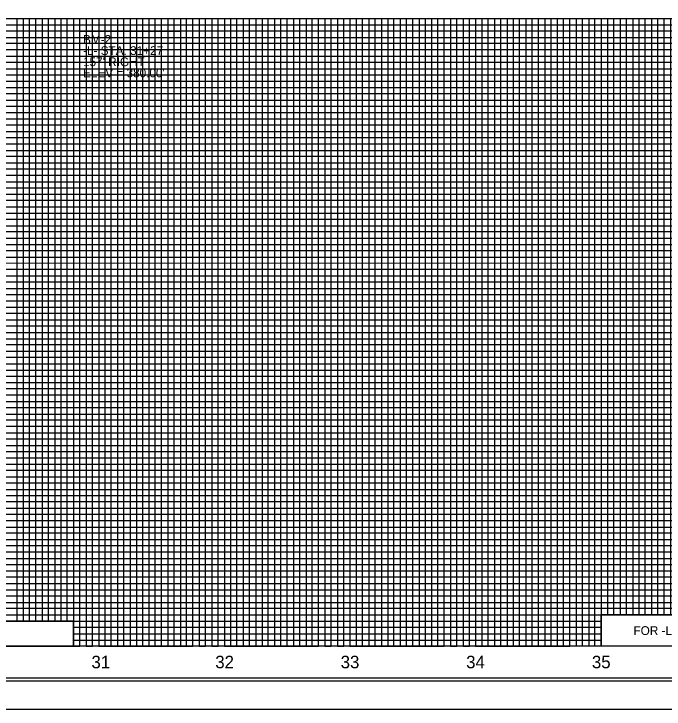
# Model space of a CAD drawing. Extents: x 1629887 to 1632095, y 1174261 to 1175361.
# Drawn here: x 1630837 to 1631354, y 1174261 to 1174814 of the extents above; entities that cross this region are included whole.
import ezdxf

# ---------------------------------------------------------------- set-up
doc = ezdxf.new("R2010")
doc.units = 0
for name, color, linetype in [('Exist Vertical Profile Horizontal Axis Label Major', 7, 'Continuous'), ('Prop DSN Text', 7, 'Continuous'), ('Prop Grid Mask', 7, 'Continuous'), ('Sheet Data Field CELL', 7, 'Continuous'), ('Sheet Layout Profile Border Port 2', 7, 'Continuous'), ('Sheet Plot Border Inside CELL', 7, 'Continuous'), ('Sheet Plot Border Outside CELL', 7, 'Continuous'), ('Sheet Profile CELL', 7, 'Continuous'), ('Sheet Profile Grid Major CELL', 7, 'Continuous'), ('Sheet Profile Grid Middle CELL', 7, 'Continuous'), ('Sheet Profile Grid Minor CELL', 7, 'Continuous')]:
    doc.layers.add(name, color=color, linetype=linetype)

msp = doc.modelspace()

# ---------------------------------------------------------------- linework, layer by layer
at = {"layer": 'Prop Grid Mask'}
msp.add_lwpolyline([(1630889.31, 1174800.79), (1630969.31, 1174800.79), (1630969.31, 1174760.79), (1630889.31, 1174760.79)], close=True, dxfattribs=at)
at = {"layer": 'Sheet Data Field CELL'}
for points in [[(1631504.31, 1174310.79), (1631304.31, 1174310.79), (1631304.31, 1174335.79), (1631504.31, 1174335.79)], [(1630724.31, 1174310.79), (1630884.31, 1174310.79), (1630884.31, 1174330.79), (1630724.31, 1174330.79)]]:
    msp.add_lwpolyline(points, close=True, dxfattribs=at)
at = {"layer": 'Sheet Layout Profile Border Port 2'}
msp.add_lwpolyline([(1630104.31, 1174810.79), (1631504.31, 1174810.79), (1631504.31, 1174335.79), (1631304.31, 1174335.79), (1631304.31, 1174310.79), (1630884.31, 1174310.79), (1630884.31, 1174330.79), (1630724.31, 1174330.79), (1630724.31, 1174310.79), (1630104.31, 1174310.79)], close=True, dxfattribs=at)
at = {"layer": 'Sheet Plot Border Inside CELL'}
msp.add_lwpolyline([(1629900.31, 1174283.24), (1631566.81, 1174283.24), (1631566.81, 1175338.34), (1629900.31, 1175338.34)], close=True, dxfattribs=at)
at = {"layer": 'Sheet Plot Border Outside CELL'}
msp.add_lwpolyline([(1629887.31, 1174260.79), (1631571.31, 1174260.79), (1631571.31, 1175360.79), (1629887.31, 1175360.79)], close=True, dxfattribs=at)
at = {"layer": 'Sheet Profile CELL'}
for p, q in [((1630054.31, 1174810.79), (1631554.31, 1174810.79)), ((1631554.31, 1174310.79), (1630054.31, 1174310.79)), ((1630054.31, 1174285.79), (1631554.31, 1174285.79))]:
    msp.add_line(p, q, dxfattribs=at)
msp.add_lwpolyline([(1631554.31, 1175335.79), (1630054.31, 1175335.79), (1630054.31, 1174285.79), (1631554.31, 1174285.79)], close=True, dxfattribs=at)
at = {"layer": 'Sheet Profile Grid Major CELL'}
for p, q in [((1630854.31, 1174810.79), (1630904.31, 1174810.79)), ((1630854.31, 1174330.79), (1630854.31, 1174810.79)), ((1630854.31, 1174810.79), (1630904.31, 1174810.79)), ((1630904.31, 1174810.79), (1630904.31, 1174310.79)), ((1630954.31, 1174810.79), (1631004.31, 1174810.79)), ((1630954.31, 1174310.79), (1630954.31, 1174810.79)), ((1630954.31, 1174810.79), (1631004.31, 1174810.79)), ((1631004.31, 1174810.79), (1631004.31, 1174310.79)), ((1631054.31, 1174810.79), (1631104.31, 1174810.79)), ((1631054.31, 1174310.79), (1631054.31, 1174810.79)), ((1631054.31, 1174810.79), (1631104.31, 1174810.79)), ((1631104.31, 1174810.79), (1631104.31, 1174310.79)), ((1631154.31, 1174810.79), (1631204.31, 1174810.79)), ((1631154.31, 1174310.79), (1631154.31, 1174810.79)), ((1631154.31, 1174810.79), (1631204.31, 1174810.79)), ((1631204.31, 1174810.79), (1631204.31, 1174310.79)), ((1631254.31, 1174810.79), (1631304.31, 1174810.79)), ((1631254.31, 1174310.79), (1631254.31, 1174810.79)), ((1631254.31, 1174810.79), (1631304.31, 1174810.79)), ((1631304.31, 1174810.79), (1631304.31, 1174310.79)), ((1630904.31, 1174310.79), (1630954.31, 1174310.79)), ((1631004.31, 1174310.79), (1631054.31, 1174310.79)), ((1631104.31, 1174310.79), (1631154.31, 1174310.79)), ((1631204.31, 1174310.79), (1631254.31, 1174310.79))]:
    msp.add_line(p, q, dxfattribs=at)
for points in [[(1631354.31, 1174335.79), (1631354.31, 1174810.79), (1631404.31, 1174810.79), (1631404.31, 1174335.79)], [(1631554.31, 1174785.79), (1630054.31, 1174785.79)], [(1631554.31, 1174735.79), (1630054.31, 1174735.79)], [(1631554.31, 1174685.79), (1630054.31, 1174685.79), (1630054.31, 1174635.79), (1631554.31, 1174635.79)], [(1631554.31, 1174585.79), (1630054.31, 1174585.79), (1630054.31, 1174535.79), (1631554.31, 1174535.79)], [(1631554.31, 1174485.79), (1630054.31, 1174485.79), (1630054.31, 1174435.79), (1631554.31, 1174435.79)], [(1631554.31, 1174385.79), (1630054.31, 1174385.79), (1630054.31, 1174385.79), (1630054.31, 1174335.79), (1631554.31, 1174335.79)], [(1631554.31, 1174310.79), (1630054.31, 1174310.79)]]:
    msp.add_lwpolyline(points, dxfattribs=at)
at = {"layer": 'Sheet Profile Grid Middle CELL'}
for points in [[(1630879.31, 1174330.79), (1630879.31, 1174810.79), (1630929.31, 1174810.79), (1630929.31, 1174310.79), (1630979.31, 1174310.79), (1630979.31, 1174810.79), (1631029.31, 1174810.79), (1631029.31, 1174310.79), (1631079.31, 1174310.79), (1631079.31, 1174810.79), (1631129.31, 1174810.79), (1631129.31, 1174310.79), (1631179.31, 1174310.79), (1631179.31, 1174810.79), (1631229.31, 1174810.79), (1631229.31, 1174310.79), (1631279.31, 1174310.79)], [(1631279.31, 1174310.79), (1631279.31, 1174810.79), (1631329.31, 1174810.79), (1631329.31, 1174335.79)], [(1630054.31, 1174760.79), (1631554.31, 1174760.79)], [(1631554.31, 1174710.79), (1630054.31, 1174710.79), (1630054.31, 1174660.79), (1631554.31, 1174660.79)], [(1631554.31, 1174610.79), (1630054.31, 1174610.79), (1630054.31, 1174560.79), (1631554.31, 1174560.79)], [(1631554.31, 1174510.79), (1630054.31, 1174510.79), (1630054.31, 1174460.79), (1631554.31, 1174460.79)], [(1631554.31, 1174410.79), (1630054.31, 1174410.79), (1630054.31, 1174360.79), (1631554.31, 1174360.79)], [(1631554.31, 1174310.79), (1630054.31, 1174310.79)]]:
    msp.add_lwpolyline(points, dxfattribs=at)
at = {"layer": 'Sheet Profile Grid Minor CELL'}
for p, q in [((1630849.31, 1174330.79), (1630849.31, 1174810.79)), ((1630849.31, 1174810.79), (1630859.31, 1174810.79)), ((1630859.31, 1174810.79), (1630859.31, 1174330.79)), ((1630864.31, 1174330.79), (1630864.31, 1174810.79)), ((1630864.31, 1174810.79), (1630869.31, 1174810.79)), ((1630869.31, 1174810.79), (1630869.31, 1174330.79)), ((1630874.31, 1174330.79), (1630874.31, 1174810.79)), ((1630874.31, 1174810.79), (1630884.31, 1174810.79)), ((1630884.31, 1174810.79), (1630884.31, 1174310.79)), ((1630889.31, 1174310.79), (1630889.31, 1174810.79)), ((1630889.31, 1174810.79), (1630894.31, 1174810.79)), ((1630894.31, 1174810.79), (1630894.31, 1174310.79)), ((1630899.31, 1174310.79), (1630899.31, 1174810.79)), ((1630899.31, 1174810.79), (1630909.31, 1174810.79)), ((1630909.31, 1174810.79), (1630909.31, 1174310.79)), ((1630914.31, 1174310.79), (1630914.31, 1174810.79)), ((1630914.31, 1174810.79), (1630919.31, 1174810.79)), ((1630919.31, 1174810.79), (1630919.31, 1174310.79)), ((1630924.31, 1174310.79), (1630924.31, 1174810.79)), ((1630924.31, 1174810.79), (1630934.31, 1174810.79)), ((1630934.31, 1174810.79), (1630934.31, 1174310.79)), ((1630104.31, 1174805.79), (1631504.31, 1174805.79)), ((1631504.31, 1174800.79), (1630104.31, 1174800.79)), ((1630104.31, 1174795.79), (1631504.31, 1174795.79)), ((1631504.31, 1174790.79), (1630104.31, 1174790.79)), ((1630104.31, 1174780.79), (1631504.31, 1174780.79)), ((1631504.31, 1174775.79), (1630104.31, 1174775.79)), ((1630104.31, 1174770.79), (1631504.31, 1174770.79)), ((1631504.31, 1174765.79), (1630104.31, 1174765.79)), ((1630104.31, 1174755.79), (1631504.31, 1174755.79)), ((1631504.31, 1174750.79), (1630104.31, 1174750.79)), ((1630104.31, 1174745.79), (1631504.31, 1174745.79)), ((1631504.31, 1174740.79), (1630104.31, 1174740.79)), ((1630104.31, 1174730.79), (1631504.31, 1174730.79)), ((1631504.31, 1174725.79), (1630104.31, 1174725.79)), ((1630104.31, 1174720.79), (1631504.31, 1174720.79)), ((1631504.31, 1174715.79), (1630104.31, 1174715.79)), ((1630104.31, 1174705.79), (1631504.31, 1174705.79)), ((1631504.31, 1174700.79), (1630104.31, 1174700.79)), ((1630104.31, 1174695.79), (1631504.31, 1174695.79)), ((1631504.31, 1174690.79), (1630104.31, 1174690.79)), ((1630104.31, 1174680.79), (1631504.31, 1174680.79)), ((1631504.31, 1174675.79), (1630104.31, 1174675.79)), ((1630104.31, 1174670.79), (1631504.31, 1174670.79)), ((1631504.31, 1174665.79), (1630104.31, 1174665.79)), ((1630104.31, 1174655.79), (1631504.31, 1174655.79)), ((1631504.31, 1174650.79), (1630104.31, 1174650.79)), ((1630104.31, 1174645.79), (1631504.31, 1174645.79)), ((1631504.31, 1174640.79), (1630104.31, 1174640.79)), ((1630104.31, 1174630.79), (1631504.31, 1174630.79)), ((1631504.31, 1174625.79), (1630104.31, 1174625.79)), ((1630104.31, 1174620.79), (1631504.31, 1174620.79)), ((1631504.31, 1174615.79), (1630104.31, 1174615.94)), ((1630104.31, 1174605.79), (1631504.31, 1174605.79)), ((1631504.31, 1174600.79), (1630104.31, 1174600.79)), ((1630104.31, 1174595.79), (1631504.31, 1174595.79)), ((1631504.31, 1174590.79), (1630104.31, 1174590.79)), ((1630104.31, 1174580.79), (1631504.31, 1174580.79)), ((1631504.31, 1174575.79), (1630104.31, 1174575.79)), ((1630104.31, 1174570.79), (1631504.31, 1174570.79)), ((1631504.31, 1174565.79), (1630104.31, 1174565.79)), ((1630104.31, 1174555.79), (1631504.31, 1174555.79)), ((1631504.31, 1174550.79), (1630104.31, 1174550.79)), ((1630104.31, 1174545.79), (1631504.31, 1174545.79)), ((1631504.31, 1174540.79), (1630104.31, 1174540.79)), ((1630104.31, 1174530.79), (1631504.31, 1174530.79)), ((1631504.31, 1174525.79), (1630104.31, 1174525.79)), ((1630104.31, 1174520.79), (1631504.31, 1174520.79)), ((1631504.31, 1174515.79), (1630104.31, 1174515.79)), ((1630104.31, 1174505.79), (1631504.31, 1174505.79)), ((1631504.31, 1174500.79), (1630104.31, 1174500.79)), ((1630104.31, 1174495.79), (1631504.31, 1174495.79)), ((1631504.31, 1174490.79), (1630104.31, 1174490.79)), ((1630104.31, 1174480.79), (1631504.31, 1174480.79)), ((1631504.31, 1174475.79), (1630104.31, 1174475.79)), ((1630104.31, 1174470.79), (1631504.31, 1174470.79)), ((1631504.31, 1174465.79), (1630104.31, 1174465.79)), ((1630104.31, 1174455.79), (1631504.31, 1174455.79)), ((1631504.31, 1174450.79), (1630104.31, 1174450.79)), ((1630104.31, 1174445.79), (1631504.31, 1174445.79)), ((1631504.31, 1174440.79), (1630104.31, 1174440.79)), ((1630104.31, 1174430.79), (1631504.31, 1174430.79)), ((1631504.31, 1174425.79), (1630104.31, 1174425.79)), ((1630104.31, 1174420.79), (1631504.31, 1174420.79)), ((1631504.31, 1174415.79), (1630104.31, 1174415.79)), ((1630104.31, 1174405.79), (1631504.31, 1174405.79)), ((1631504.31, 1174400.79), (1630104.31, 1174400.79)), ((1630104.31, 1174395.79), (1631504.31, 1174395.79)), ((1631504.31, 1174390.79), (1630104.31, 1174390.79)), ((1630104.31, 1174380.79), (1631504.31, 1174380.79)), ((1631504.31, 1174375.79), (1630104.31, 1174375.79)), ((1630104.31, 1174370.79), (1631504.31, 1174370.79)), ((1631504.31, 1174365.79), (1630104.31, 1174365.79)), ((1630104.31, 1174355.79), (1631504.31, 1174355.79)), ((1631504.31, 1174350.79), (1630104.31, 1174350.79)), ((1630104.31, 1174345.79), (1631504.31, 1174345.79)), ((1631504.31, 1174340.79), (1630104.31, 1174340.79)), ((1630104.31, 1174330.79), (1631304.31, 1174330.79)), ((1631304.31, 1174325.79), (1630884.31, 1174325.79)), ((1630884.31, 1174320.79), (1631304.31, 1174320.79)), ((1630884.31, 1174315.79), (1631304.31, 1174315.79)), ((1630884.31, 1174310.79), (1630889.31, 1174310.79)), ((1630894.31, 1174310.79), (1630899.31, 1174310.79)), ((1630909.31, 1174310.79), (1630914.31, 1174310.79)), ((1630919.31, 1174310.79), (1630924.31, 1174310.79)), ((1630934.31, 1174310.79), (1630939.31, 1174310.79))]:
    msp.add_line(p, q, dxfattribs=at)
for points in [[(1630839.31, 1174330.79), (1630839.31, 1174810.79), (1630844.31, 1174810.79), (1630844.31, 1174330.79)], [(1630939.31, 1174310.79), (1630939.31, 1174810.79), (1630944.31, 1174810.79), (1630944.31, 1174310.79), (1630949.31, 1174310.79), (1630949.31, 1174810.79), (1630959.31, 1174810.79), (1630959.31, 1174310.79), (1630964.31, 1174310.79), (1630964.31, 1174810.79), (1630969.31, 1174810.79), (1630969.31, 1174310.79), (1630974.31, 1174310.79), (1630974.31, 1174810.79), (1630984.31, 1174810.79), (1630984.31, 1174310.79), (1630989.31, 1174310.79), (1630989.31, 1174810.79), (1630994.31, 1174810.79), (1630994.31, 1174310.79), (1630999.31, 1174310.79), (1630999.31, 1174810.79), (1631009.31, 1174810.79), (1631009.31, 1174310.79), (1631014.31, 1174310.79), (1631014.31, 1174810.79), (1631019.31, 1174810.79), (1631019.31, 1174310.79), (1631024.31, 1174310.79), (1631024.31, 1174810.79), (1631034.31, 1174810.79), (1631034.31, 1174310.79), (1631039.31, 1174310.79), (1631039.31, 1174810.79), (1631044.31, 1174810.79), (1631044.31, 1174310.79), (1631049.31, 1174310.79), (1631049.31, 1174810.79), (1631059.31, 1174810.79), (1631059.31, 1174310.79), (1631064.31, 1174310.79), (1631064.31, 1174810.79), (1631069.31, 1174810.79), (1631069.31, 1174310.79), (1631074.31, 1174310.79), (1631074.31, 1174810.79), (1631084.31, 1174810.79), (1631084.31, 1174310.79), (1631089.31, 1174310.79), (1631089.31, 1174810.79), (1631094.31, 1174810.79), (1631094.31, 1174310.79), (1631099.31, 1174310.79), (1631099.31, 1174810.79), (1631109.31, 1174810.79), (1631109.31, 1174310.79), (1631114.31, 1174310.79), (1631114.31, 1174810.79), (1631119.31, 1174810.79), (1631119.31, 1174310.79), (1631124.31, 1174310.79), (1631124.31, 1174810.79), (1631134.31, 1174810.79), (1631134.31, 1174310.79), (1631139.31, 1174310.79), (1631139.31, 1174810.79), (1631144.31, 1174810.79), (1631144.31, 1174310.79), (1631149.31, 1174310.79), (1631149.31, 1174810.79), (1631159.31, 1174810.79), (1631159.31, 1174310.79), (1631164.31, 1174310.79), (1631164.31, 1174810.79), (1631169.31, 1174810.79), (1631169.31, 1174310.79), (1631174.31, 1174310.79), (1631174.31, 1174810.79), (1631184.31, 1174810.79), (1631184.31, 1174310.79), (1631189.31, 1174310.79), (1631189.31, 1174810.79), (1631194.31, 1174810.79), (1631194.31, 1174310.79), (1631199.31, 1174310.79), (1631199.31, 1174810.79), (1631209.31, 1174810.79), (1631209.31, 1174310.79), (1631214.31, 1174310.79), (1631214.31, 1174810.79), (1631219.31, 1174810.79), (1631219.31, 1174310.79), (1631224.31, 1174310.79), (1631224.31, 1174810.79), (1631234.31, 1174810.79), (1631234.31, 1174310.79), (1631239.31, 1174310.79), (1631239.31, 1174810.79), (1631244.31, 1174810.79), (1631244.31, 1174310.79)], [(1631244.31, 1174310.79), (1631249.31, 1174310.79), (1631249.31, 1174810.79), (1631259.31, 1174810.79), (1631259.31, 1174310.79)], [(1631264.31, 1174310.79), (1631264.31, 1174810.79), (1631269.31, 1174810.79), (1631269.31, 1174310.79)], [(1631274.31, 1174310.79), (1631274.31, 1174810.79), (1631284.31, 1174810.79), (1631284.31, 1174310.79)], [(1631289.31, 1174310.79), (1631289.31, 1174810.79), (1631294.31, 1174810.79), (1631294.31, 1174310.79)], [(1631299.31, 1174310.79), (1631299.31, 1174810.79), (1631309.31, 1174810.79), (1631309.31, 1174335.79)], [(1631314.31, 1174335.79), (1631314.31, 1174810.79), (1631319.31, 1174810.79), (1631319.31, 1174335.79)], [(1631324.31, 1174335.79), (1631324.31, 1174810.79), (1631334.31, 1174810.79), (1631334.31, 1174335.79)], [(1631339.31, 1174335.79), (1631339.31, 1174810.79), (1631344.31, 1174810.79), (1631344.31, 1174335.79)], [(1631349.31, 1174335.79), (1631349.31, 1174810.79), (1631359.31, 1174810.79), (1631359.31, 1174335.79)]]:
    msp.add_lwpolyline(points, dxfattribs=at)

# ---------------------------------------------------------------- texts
at = {"layer": 'Exist Vertical Profile Horizontal Axis Label Major'}
for s, p in [('31', (1630898.54, 1174293.29)), ('32', (1630997.09, 1174293.29)), ('33', (1631096.92, 1174293.29)), ('34', (1631196.77, 1174293.29)), ('35', (1631296.86, 1174293.29))]:
    msp.add_text(s, height=10, dxfattribs=at).set_placement(p)
at = {"layer": 'Prop DSN Text'}
for s, p in [('BM-2', (1630891.84, 1174790.6)), ('-L- STA. 31+27', (1630891.84, 1174781.72)), ("157' RIGHT", (1630891.84, 1174772.85)), ("ELEV = 380.00'", (1630891.84, 1174763.97))]:
    msp.add_text(s, height=7, rotation=360, dxfattribs=at).set_placement(p)
at = {"layer": 'Sheet Data Field CELL'}
msp.add_text('FOR -L- PLAN, SEE SHEET 5 & 6', height=7, rotation=360, dxfattribs=at).set_placement((1631329.96, 1174319.79))

doc.saveas('drawing.dxf')
